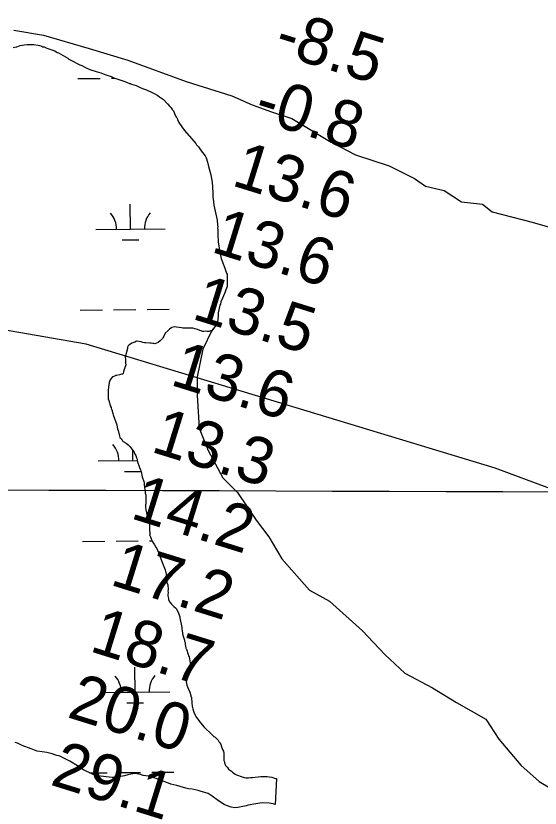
# Model space of a CAD drawing. Extents: x 3146026 to 3183936, y 897894 to 923344.
# Drawn here: x 3152037 to 3152791, y 915037 to 916175 of the extents above; entities that cross this region are included whole.
import ezdxf

# ---------------------------------------------------------------- set-up
doc = ezdxf.new("R2010")
doc.units = 0
for name, color, linetype in [('V-GRID-MAJR', 7, 'Continuous'), ('V-RIVR-EDGE', 7, 'Continuous'), ('V-RIVR-RANG', 7, 'Continuous'), ('V-SITE-VEGE', 7, 'Continuous'), ('V-TOPO-BNDY', 7, 'Continuous'), ('V-WETL-SWMP', 7, 'Continuous')]:
    doc.layers.add(name, color=color, linetype=linetype)

msp = doc.modelspace()

# ---------------------------------------------------------------- linework, layer by layer
at = {"layer": 'V-GRID-MAJR'}
msp.add_spline([(3150289.9, 915500.2), (3155511.6, 915481.6), (3160733.3, 915463.8), (3165955, 915446.7), (3171176.8, 915430.3), (3176398.5, 915414.8), (3181620.2, 915400)], degree=3, dxfattribs=at)
at = {"layer": 'V-RIVR-EDGE'}
for points in [[(3152034.6, 916154.7), (3152077, 916147.5), (3152142.8, 916128.3), (3152198.3, 916111.5), (3152282.3, 916080.7), (3152348.1, 916060.4), (3152377, 916047.2), (3152404.7, 916037.2), (3152434, 916027.6), (3152490.7, 915993.8), (3152525.5, 915975.4), (3152574.3, 915959.9), (3152610.7, 915941.5), (3152626.6, 915930.4), (3152653.1, 915924.4)], [(3152653.1, 915924.4), (3152678.1, 915908), (3152708.2, 915904.4), (3152722.4, 915893.7), (3152779.9, 915878.8), (3152826.3, 915865.2)]]:
    msp.add_lwpolyline(points, dxfattribs=at)
at = {"layer": 'V-SITE-VEGE'}
for p, q in [((3152033.3, 916129.6), (3152037.5, 916130.8)), ((3152037.5, 916130.8), (3152038.7, 916130.8)), ((3152038.7, 916130.8), (3152043.3, 916132.5)), ((3152043.3, 916132.5), (3152049.2, 916133.4)), ((3152049.2, 916133.4), (3152053.4, 916133.8)), ((3152053.4, 916133.8), (3152063.1, 916133.8)), ((3152063.1, 916133.8), (3152069.4, 916133)), ((3152069.4, 916133), (3152071.5, 916132.6)), ((3152071.5, 916132.6), (3152074.4, 916131.8)), ((3152074.4, 916131.8), (3152076.1, 916130.9)), ((3152076.1, 916130.9), (3152078.2, 916130.5)), ((3152078.2, 916130.5), (3152082, 916128.8)), ((3152082, 916128.8), (3152093.3, 916124.7)), ((3152093.3, 916124.7), (3152096.7, 916122.6)), ((3152096.7, 916122.6), (3152098.4, 916122.1)), ((3152098.4, 916122.1), (3152112.2, 916114.2)), ((3152112.2, 916114.2), (3152113.5, 916112.9)), ((3152113.5, 916112.9), (3152116.5, 916111.3)), ((3152116.5, 916111.3), (3152129.1, 916105)), ((3152129.1, 916105), (3152132, 916103.8)), ((3152132, 916103.8), (3152137.5, 916100.8)), ((3152137.5, 916100.8), (3152143.8, 916098.3)), ((3152143.8, 916098.3), (3152153, 916095.4)), ((3152153, 916095.4), (3152156, 916094.1)), ((3152156, 916094.1), (3152159.3, 916093.3)), ((3152159.3, 916093.3), (3152166.5, 916090.4)), ((3152166.5, 916090.4), (3152174.5, 916087.9)), ((3152174.5, 916087.9), (3152178.2, 916086.2)), ((3152178.2, 916086.2), (3152181.2, 916085.4)), ((3152181.2, 916085.4), (3152184.1, 916084.1)), ((3152184.1, 916084.1), (3152188.3, 916082.9)), ((3152188.3, 916082.9), (3152194.2, 916080.8)), ((3152194.2, 916080.8), (3152196.3, 916080)), ((3152196.3, 916080), (3152200.5, 916077.9)), ((3152200.5, 916077.9), (3152201.8, 916077.9)), ((3152201.8, 916077.9), (3152203.5, 916077)), ((3152203.5, 916077), (3152210.2, 916075)), ((3152210.2, 916075), (3152215.2, 916072.9)), ((3152215.2, 916072.9), (3152219.4, 916070.8)), ((3152219.4, 916070.8), (3152225.3, 916068.7)), ((3152225.3, 916068.7), (3152234.1, 916064.5)), ((3152234.1, 916064.5), (3152241.3, 916060.8)), ((3152241.3, 916060.8), (3152243.8, 916058.7)), ((3152243.8, 916058.7), (3152248, 916056.1)), ((3152248, 916056.1), (3152249.7, 916054.9)), ((3152249.7, 916054.9), (3152255.6, 916049)), ((3152255.6, 916049), (3152258.5, 916044.8)), ((3152258.5, 916044.8), (3152260.6, 916043.2)), ((3152260.6, 916043.2), (3152262.3, 916040.6)), ((3152262.3, 916040.6), (3152264, 916038.6)), ((3152264, 916038.6), (3152266.5, 916032.7)), ((3152266.5, 916032.7), (3152268.2, 916029.3)), ((3152268.2, 916029.3), (3152269.1, 916028.1)), ((3152269.1, 916028.1), (3152269.9, 916026.4)), ((3152269.9, 916026.4), (3152271.6, 916021.8)), ((3152271.6, 916021.8), (3152275.8, 916015.5)), ((3152275.8, 916015.5), (3152279.6, 916010.5)), ((3152279.6, 916010.5), (3152285.9, 916003.3)), ((3152285.9, 916003.3), (3152286.8, 916002.1)), ((3152286.8, 916002.1), (3152287.2, 916002.1)), ((3152287.2, 916002.1), (3152290.1, 915999.1)), ((3152290.1, 915999.1), (3152296, 915992)), ((3152296, 915992), (3152297.3, 915989.9)), ((3152297.3, 915989.9), (3152299.8, 915987)), ((3152299.8, 915987), (3152303.6, 915981.1)), ((3152303.6, 915981.1), (3152305.7, 915979)), ((3152305.7, 915979), (3152309.5, 915974)), ((3152309.5, 915974), (3152310.8, 915971.1)), ((3152310.8, 915971.1), (3152312.9, 915964.8)), ((3152312.9, 915964.8), (3152314.2, 915958.9)), ((3152314.2, 915958.9), (3152317.5, 915946.7)), ((3152317.5, 915946.7), (3152319.7, 915936.2)), ((3152319.7, 915936.2), (3152319.7, 915934.1)), ((3152319.7, 915934.1), (3152320.1, 915930.8)), ((3152320.1, 915930.8), (3152320.1, 915928.2)), ((3152320.1, 915928.2), (3152320.5, 915921.9)), ((3152320.5, 915921.9), (3152320.6, 915914.4)), ((3152320.6, 915914.4), (3152321, 915912.3)), ((3152321, 915912.3), (3152321.8, 915903.1)), ((3152321.8, 915903.1), (3152326.9, 915881.7)), ((3152326.9, 915881.7), (3152327.4, 915874.5)), ((3152327.4, 915874.5), (3152327.8, 915872)), ((3152327.8, 915872), (3152327.4, 915870.3)), ((3152327.4, 915870.3), (3152327.8, 915869.1)), ((3152327.8, 915869.1), (3152327.8, 915857.7)), ((3152327.8, 915857.7), (3152328.3, 915853.9)), ((3152328.3, 915853.9), (3152328.3, 915850.6)), ((3152328.3, 915850.6), (3152330.8, 915835.1)), ((3152330.8, 915835.1), (3152332.5, 915826.7)), ((3152332.5, 915826.7), (3152333.8, 915822.5)), ((3152333.8, 915822.5), (3152337.6, 915812.8)), ((3152337.6, 915812.8), (3152340.1, 915805.3)), ((3152340.1, 915805.3), (3152341, 915804)), ((3152341, 915804), (3152341.4, 915801.9)), ((3152341.4, 915801.9), (3152341.4, 915788.5)), ((3152341, 915786.4), (3152339.3, 915781.3)), ((3152341.4, 915788.5), (3152341, 915786.4)), ((3152337.3, 915776.3), (3152334.3, 915769.6)), ((3152338.1, 915778.8), (3152337.3, 915776.3)), ((3152339.3, 915781.3), (3152338.1, 915778.8)), ((3152330.6, 915759.5), (3152328.1, 915748.5)), ((3152331.4, 915760.7), (3152330.6, 915759.5)), ((3152332.2, 915764.1), (3152331.4, 915760.7)), ((3152334.3, 915769.6), (3152332.2, 915764.1)), ((3152328.1, 915748.5), (3152328.1, 915743.5)), ((3152328.1, 915743.5), (3152327.3, 915735.1)), ((3152324.3, 915729.6), (3152319.2, 915722.9)), ((3152327.3, 915735.1), (3152324.3, 915729.6)), ((3152319.2, 915722.9), (3152306, 915696.3)), ((3152306, 915696.3), (3152298.1, 915656.6)), ((3152298.1, 915656.6), (3152298.1, 915630.1)), ((3152298.1, 915630.1), (3152300.7, 915582.5)), ((3152300.7, 915582.5), (3152313.9, 915550.8)), ((3152313.9, 915550.8), (3152335.1, 915511.1)), ((3152335.1, 915511.1), (3152356.2, 915490)), ((3152356.2, 915490), (3152382.7, 915450.3)), ((3152382.7, 915450.3), (3152401.2, 915426.5)), ((3152401.2, 915426.5), (3152419.7, 915394.7)), ((3152419.7, 915394.7), (3152459.4, 915349.8)), ((3152459.4, 915349.8), (3152488.4, 915333.9)), ((3152488.4, 915333.9), (3152536, 915291.6)), ((3152536, 915291.6), (3152567.8, 915257.2)), ((3152567.8, 915257.2), (3152596.9, 915230.7)), ((3152596.9, 915230.7), (3152636.5, 915209.6)), ((3152636.5, 915209.6), (3152670.9, 915188.4)), ((3152670.9, 915188.4), (3152713.2, 915164.6)), ((3152713.2, 915164.6), (3152731.7, 915135.5)), ((3152731.7, 915135.5), (3152763.4, 915098.5)), ((3152763.4, 915098.5), (3152789.9, 915074.7)), ((3152789.9, 915074.7), (3152848, 915040.3))]:
    msp.add_line(p, q, dxfattribs=at)
at = {"layer": 'V-TOPO-BNDY'}
msp.add_lwpolyline([(3157135.3, 913454.6), (3156545.8, 913785.7), (3156046.8, 914087.9), (3155569.3, 914332.3), (3155069.9, 914586.2), (3154635.6, 914773.9), (3154205.8, 914944.7), (3153750.9, 915119.9), (3153426.5, 915265.2), (3152726.4, 915525.1), (3152138.2, 915703.5), (3151800.3, 915761.8), (3151784, 915764.6), (3151638.6, 916007.3), (3151536, 916215.7), (3151471.7, 916347.2), (3151446.4, 916455.9), (3151405.1, 916635.1), (3151355.7, 916974.3), (3151353.5, 917141.4), (3151352.6, 917210), (3151351.8, 917287.8)], dxfattribs=at)
at = {"layer": 'V-WETL-SWMP'}
for p, q in [((3152126.6, 916085.1), (3152158.6, 916085.4)), ((3152174.6, 916085.6), (3152180.3, 916085.6)), ((3152202.2, 915868.6), (3152201.8, 915904.6)), ((3152152.2, 915868.1), (3152252.2, 915869.1)), ((3152190.3, 915853.1), (3152214.3, 915853.3)), ((3152129.9, 915752.4), (3152161.9, 915752.8)), ((3152177.9, 915752.9), (3152209.9, 915753.2)), ((3152225.9, 915753.4), (3152257.9, 915753.7)), ((3152205.5, 915536), (3152205.4, 915551)), ((3152155.5, 915535.5), (3152212, 915536)), ((3152193.7, 915520.4), (3152217.4, 915520.6)), ((3152133.3, 915419.8), (3152165.3, 915420.1)), ((3152181.3, 915420.3), (3152213.3, 915420.6)), ((3152229.3, 915420.8), (3152233.1, 915420.8)), ((3152208.8, 915203.3), (3152208.5, 915239.3)), ((3152158.8, 915202.8), (3152258.8, 915203.8)), ((3152197, 915187.7), (3152221, 915188)), ((3152184.6, 915087.6), (3152216.6, 915087.9)), ((3152232.6, 915088.1), (3152264.6, 915088.4)), ((3152143.3, 915087.2), (3152168.6, 915087.5))]:
    msp.add_line(p, q, dxfattribs=at)
for points in [[(3152033.3, 916129.6), (3152037.5, 916130.8), (3152038.7, 916130.8), (3152043.3, 916132.5), (3152049.2, 916133.4), (3152053.4, 916133.8), (3152063.1, 916133.8), (3152069.4, 916133)], [(3152069.4, 916133), (3152071.5, 916132.6), (3152074.4, 916131.8), (3152076.1, 916130.9), (3152078.2, 916130.5), (3152082, 916128.8), (3152093.3, 916124.7), (3152096.7, 916122.6), (3152098.4, 916122.1), (3152112.2, 916114.2), (3152113.5, 916112.9), (3152116.5, 916111.3), (3152129.1, 916105), (3152132, 916103.8), (3152137.5, 916100.8), (3152143.8, 916098.3), (3152153, 916095.4), (3152156, 916094.1), (3152159.3, 916093.3), (3152166.5, 916090.4), (3152174.5, 916087.9), (3152178.2, 916086.2), (3152181.2, 916085.4), (3152184.1, 916084.1), (3152188.3, 916082.9), (3152194.2, 916080.8), (3152196.3, 916080), (3152200.5, 916077.9), (3152201.8, 916077.9), (3152203.5, 916077), (3152210.2, 916075), (3152215.2, 916072.9), (3152219.4, 916070.8), (3152225.3, 916068.7), (3152234.1, 916064.5), (3152241.3, 916060.8), (3152243.8, 916058.7), (3152248, 916056.1), (3152249.7, 916054.9), (3152255.6, 916049), (3152258.5, 916044.8), (3152260.6, 916043.2), (3152262.3, 916040.6), (3152264, 916038.5), (3152266.5, 916032.7)], [(3152266.5, 916032.7), (3152268.2, 916029.3), (3152269.1, 916028.1), (3152269.9, 916026.4), (3152271.6, 916021.8), (3152275.8, 916015.5), (3152279.6, 916010.5), (3152285.9, 916003.3), (3152286.8, 916002.1), (3152287.2, 916002.1), (3152290.1, 915999.1), (3152296, 915992), (3152297.3, 915989.9), (3152299.8, 915987), (3152303.6, 915981.1), (3152305.7, 915979), (3152309.5, 915974), (3152310.8, 915971.1), (3152312.9, 915964.8), (3152314.2, 915958.9), (3152317.5, 915946.7), (3152319.7, 915936.2), (3152319.7, 915934.1), (3152320.1, 915930.8), (3152320.1, 915928.2), (3152320.5, 915921.9), (3152320.6, 915914.4), (3152321, 915912.3), (3152321.8, 915903.1), (3152326.9, 915881.7), (3152327.4, 915874.5), (3152327.8, 915872), (3152327.4, 915870.3), (3152327.8, 915869.1), (3152327.8, 915857.7), (3152328.3, 915853.9), (3152328.3, 915850.6), (3152330.8, 915835.1), (3152332.5, 915826.7), (3152333.8, 915822.5), (3152337.6, 915812.8), (3152340.1, 915805.3), (3152341, 915804), (3152341.4, 915801.9), (3152341.4, 915788.5), (3152341, 915786.4), (3152339.3, 915781.3), (3152338.1, 915778.8), (3152337.3, 915776.3), (3152334.3, 915769.6), (3152332.2, 915764.1), (3152331.4, 915760.7), (3152330.6, 915759.5), (3152328.1, 915748.5), (3152328.1, 915743.5), (3152327.3, 915735.1), (3152324.3, 915729.6), (3152318.9, 915722.5), (3152317.6, 915722.5), (3152314.7, 915721.6), (3152312.2, 915721.6), (3152309.7, 915722.1), (3152307.6, 915721.6), (3152305.5, 915721.6), (3152303.8, 915722.5), (3152301.7, 915722.9), (3152298.7, 915724.5), (3152291.6, 915726.2), (3152287.8, 915726.6), (3152283.6, 915726.6), (3152281.1, 915726.2), (3152279, 915726.6), (3152277.3, 915726.6), (3152275.6, 915727), (3152265.1, 915728.2), (3152261.8, 915727.4), (3152258.4, 915724.9), (3152256.3, 915722.8), (3152252.1, 915719), (3152250.1, 915714.8), (3152248.8, 915712.7), (3152248, 915711.4), (3152246.3, 915709.7), (3152245, 915708), (3152242.1, 915705.9), (3152239.6, 915704.7), (3152237.1, 915703.8), (3152235.8, 915704.2), (3152234.1, 915704.2), (3152232, 915704.7), (3152229.9, 915704.7), (3152223.6, 915705.5), (3152222.4, 915705.5), (3152219.8, 915705.9), (3152217.3, 915706.7), (3152211, 915707.5), (3152208.5, 915706.3), (3152204.3, 915704.6), (3152202.2, 915703.3), (3152199.7, 915702.1), (3152198.9, 915700.8)], [(3152198.9, 915700.8), (3152198, 915699.1), (3152198, 915697), (3152194.7, 915684.8), (3152195.1, 915681.9), (3152195.1, 915676), (3152195.6, 915673.9), (3152193.1, 915667.2), (3152192.2, 915663.4), (3152191.4, 915661.7), (3152191, 915660.5), (3152189.7, 915660.5), (3152188, 915659.6), (3152186.4, 915659.2), (3152182.2, 915658.4), (3152180.9, 915658.3), (3152179.6, 915657.5), (3152176.3, 915656.2), (3152173.8, 915653.7), (3152172.5, 915651.2), (3152171.7, 915648.3), (3152170.4, 915641.5), (3152170, 915636.9), (3152170.1, 915624.7), (3152170.9, 915622.2), (3152171.3, 915620.1), (3152172.2, 915618), (3152173, 915614.7), (3152174.3, 915612.6), (3152174.3, 915611.3), (3152174.7, 915609.6), (3152175.6, 915608.4), (3152175.6, 915607.1), (3152176.8, 915603.8), (3152177.3, 915601.7), (3152182.3, 915587.4), (3152183.2, 915584), (3152183.6, 915581.5), (3152184.4, 915579.4), (3152186.1, 915571.4), (3152187, 915569.3), (3152189.1, 915567.2), (3152190.8, 915564.3), (3152191.6, 915563.5), (3152195.8, 915561), (3152198.8, 915558.9), (3152201.3, 915556.4), (3152207.6, 915548), (3152208, 915546.3), (3152208.9, 915544.6), (3152209.7, 915543.4), (3152211, 915540), (3152211.8, 915538.3), (3152211.8, 915537.1), (3152212.3, 915534.1), (3152214.8, 915527.8), (3152215.2, 915526.2), (3152216.5, 915522.8), (3152216.9, 915521.1), (3152217.7, 915520.3), (3152219, 915512.7), (3152221.1, 915506), (3152222, 915504.3), (3152222, 915501.8), (3152222.4, 915497.2), (3152223.3, 915491.7), (3152223.3, 915489.2), (3152224.1, 915486.7), (3152224.2, 915473.7), (3152223.7, 915472.4), (3152223.7, 915469.1), (3152224.2, 915465.3), (3152226.3, 915456.9), (3152226.3, 915455.6), (3152227.6, 915451), (3152228, 915448.1), (3152229.3, 915444.7), (3152229.3, 915443.5), (3152229.3, 915435.9), (3152230.1, 915431.7), (3152230.6, 915430.5), (3152229.7, 915429.6), (3152231, 915426.7), (3152231.8, 915423.7), (3152233.1, 915420.8), (3152233.9, 915419.5), (3152234.8, 915417.9), (3152236.5, 915414.9), (3152238.6, 915411.6), (3152239.8, 915409.9), (3152241.9, 915404.9), (3152242.8, 915403.6), (3152245.3, 915396.5), (3152247, 915391), (3152248.3, 915388.5), (3152252.1, 915379.3), (3152253.4, 915373), (3152253.4, 915371.7), (3152253.8, 915369.2), (3152253.8, 915367.5), (3152254.6, 915362.9)], [(3152254.6, 915362.9), (3152254.6, 915360.8), (3152255.9, 915357.5), (3152256.4, 915350.7), (3152255.9, 915348.2), (3152256.4, 915346.5), (3152255.9, 915343.6), (3152256, 915341.5), (3152256.8, 915337.7), (3152256.8, 915336), (3152258.5, 915332.7), (3152261, 915329.8), (3152264.4, 915326.4), (3152266.9, 915324.3), (3152268.2, 915323), (3152271.1, 915316.8), (3152273.2, 915311.3), (3152273.2, 915310), (3152276.2, 915296.2), (3152276.2, 915293.7), (3152276.6, 915292), (3152277.1, 915287.4), (3152277.5, 915285.3), (3152279.2, 915279.4), (3152280, 915278.1), (3152280, 915276.5), (3152280.9, 915274.8), (3152280.9, 915271.9), (3152281.7, 915267.2), (3152282.2, 915266.4), (3152281.7, 915266), (3152282.6, 915265.1), (3152285.1, 915257.6), (3152285.5, 915255.5), (3152286.4, 915254.2), (3152287.2, 915251.3), (3152288.5, 915242.5), (3152287.7, 915239.1), (3152285.6, 915233.7), (3152284.8, 915230.7), (3152283.1, 915226.9), (3152283.1, 915225.7), (3152282.7, 915222.3), (3152282.7, 915219.4), (3152282.3, 915218.1), (3152283.1, 915213.5), (3152284, 915211), (3152285.7, 915207.6), (3152287.3, 915203.4), (3152289, 915198.4), (3152289, 915196.7), (3152289.9, 915195.9), (3152289.9, 915193.8), (3152290.3, 915189.6), (3152290.3, 915186.6), (3152290.7, 915184.5), (3152290.7, 915183.3), (3152291.6, 915179.5), (3152292.9, 915176.1), (3152293.7, 915173.2), (3152297.1, 915166.9), (3152300.5, 915162.7), (3152301.3, 915161), (3152303.4, 915158.9), (3152307.6, 915153.5), (3152319.4, 915141.8), (3152321.9, 915139.7), (3152324, 915138.4), (3152328.2, 915134.2), (3152329.9, 915131.3), (3152330.8, 915130.5), (3152332, 915128.4), (3152332.4, 915126.3), (3152334.6, 915120.8), (3152335.8, 915118.3), (3152336.3, 915114.9), (3152336.3, 915104.9), (3152337.1, 915103.2), (3152337.1, 915101.5), (3152338.8, 915098.1), (3152340.1, 915096.5), (3152341.8, 915094.8), (3152343, 915092.7), (3152347.2, 915089.8), (3152348.9, 915088.1), (3152352.7, 915085.2), (3152354.4, 915084.7), (3152362.8, 915081.4), (3152365.7, 915080.6), (3152367.8, 915080.2), (3152371.6, 915080.2), (3152374.5, 915080.6), (3152377.5, 915080.6), (3152389.7, 915081.9), (3152393, 915081.9), (3152394.7, 915082.3), (3152398.5, 915082.3), (3152401.8, 915081.5), (3152405.2, 915081.1), (3152410.7, 915079.4), (3152411.9, 915079.4)], [(3152411.9, 915079.4), (3152410.3, 915041.7), (3152407.4, 915042.6), (3152401.5, 915043.8), (3152392.3, 915044.2), (3152388.1, 915043.8), (3152382.2, 915042.9), (3152371.3, 915040.8), (3152368.4, 915040), (3152356.6, 915037.4), (3152352.4, 915037), (3152347, 915038.2), (3152340.2, 915040.3), (3152336.9, 915041.6), (3152328.9, 915047), (3152319.6, 915053.7), (3152313.7, 915057.5), (3152302.4, 915061.2), (3152299.4, 915062.1), (3152291, 915063.7), (3152285.6, 915064.5), (3152281.8, 915065.4), (3152273.4, 915067.5), (3152268.8, 915069.1), (3152260, 915071.2), (3152257, 915072.5), (3152254.1, 915073.3), (3152248.2, 915075.8), (3152238.9, 915079.1), (3152233.1, 915080.8), (3152228, 915082.5), (3152220.5, 915083.7), (3152216.3, 915085), (3152209.1, 915086.2), (3152202.8, 915085.4), (3152198.2, 915084.5), (3152193.6, 915083.2), (3152185.6, 915081.5), (3152180.6, 915080.7), (3152176, 915080.7), (3152154.5, 915083.1), (3152150.8, 915084), (3152147.4, 915085.2), (3152134.4, 915091.5), (3152128.5, 915095.3), (3152125.9, 915097.4), (3152115, 915104), (3152102.4, 915110.3), (3152099.5, 915111.6), (3152096.1, 915112.4), (3152089.4, 915114.5), (3152081.8, 915116.6), (3152075.1, 915117.4), (3152068, 915118.6), (3152064.2, 915119.9), (3152059.5, 915122), (3152046.5, 915126.6), (3152043.6, 915128.2), (3152039.8, 915129.9), (3152036.4, 915130.7)]]:
    msp.add_lwpolyline(points, dxfattribs=at)
for centre, start, end in [((3152146.9, 915868.5), 359.7992, 41.3429), ((3152257.4, 915869.6), 139.7992, 181.3429), ((3152150.3, 915535.9), 359.7992, 41.3429), ((3152153.6, 915203.2), 359.7992, 41.3429), ((3152264.1, 915204.3), 139.7992, 181.3429)]:
    msp.add_arc(centre, 35.2, start, end, dxfattribs=at)

# ---------------------------------------------------------------- texts
at = {"layer": 'V-RIVR-RANG'}
for s, p in [('-8.5', (3152406.4, 916122.7)), ('-0.8', (3152377, 916027.1)), ('13.6', (3152345.8, 915932.1)), ('13.6', (3152316.3, 915836.5)), ('13.5', (3152288.7, 915740.4)), ('13.6', (3152257.5, 915645.4)), ('13.3', (3152229.8, 915549.3)), ('14.2', (3152200.4, 915453.7)), ('17.2', (3152171, 915358.1)), ('18.7', (3152141.5, 915262.6)), ('20.0', (3152109.3, 915167.8)), ('29.1', (3152084.9, 915070.7))]:
    msp.add_text(s, height=67, rotation=342.7483, dxfattribs=at).set_placement(p)

doc.saveas('drawing.dxf')
